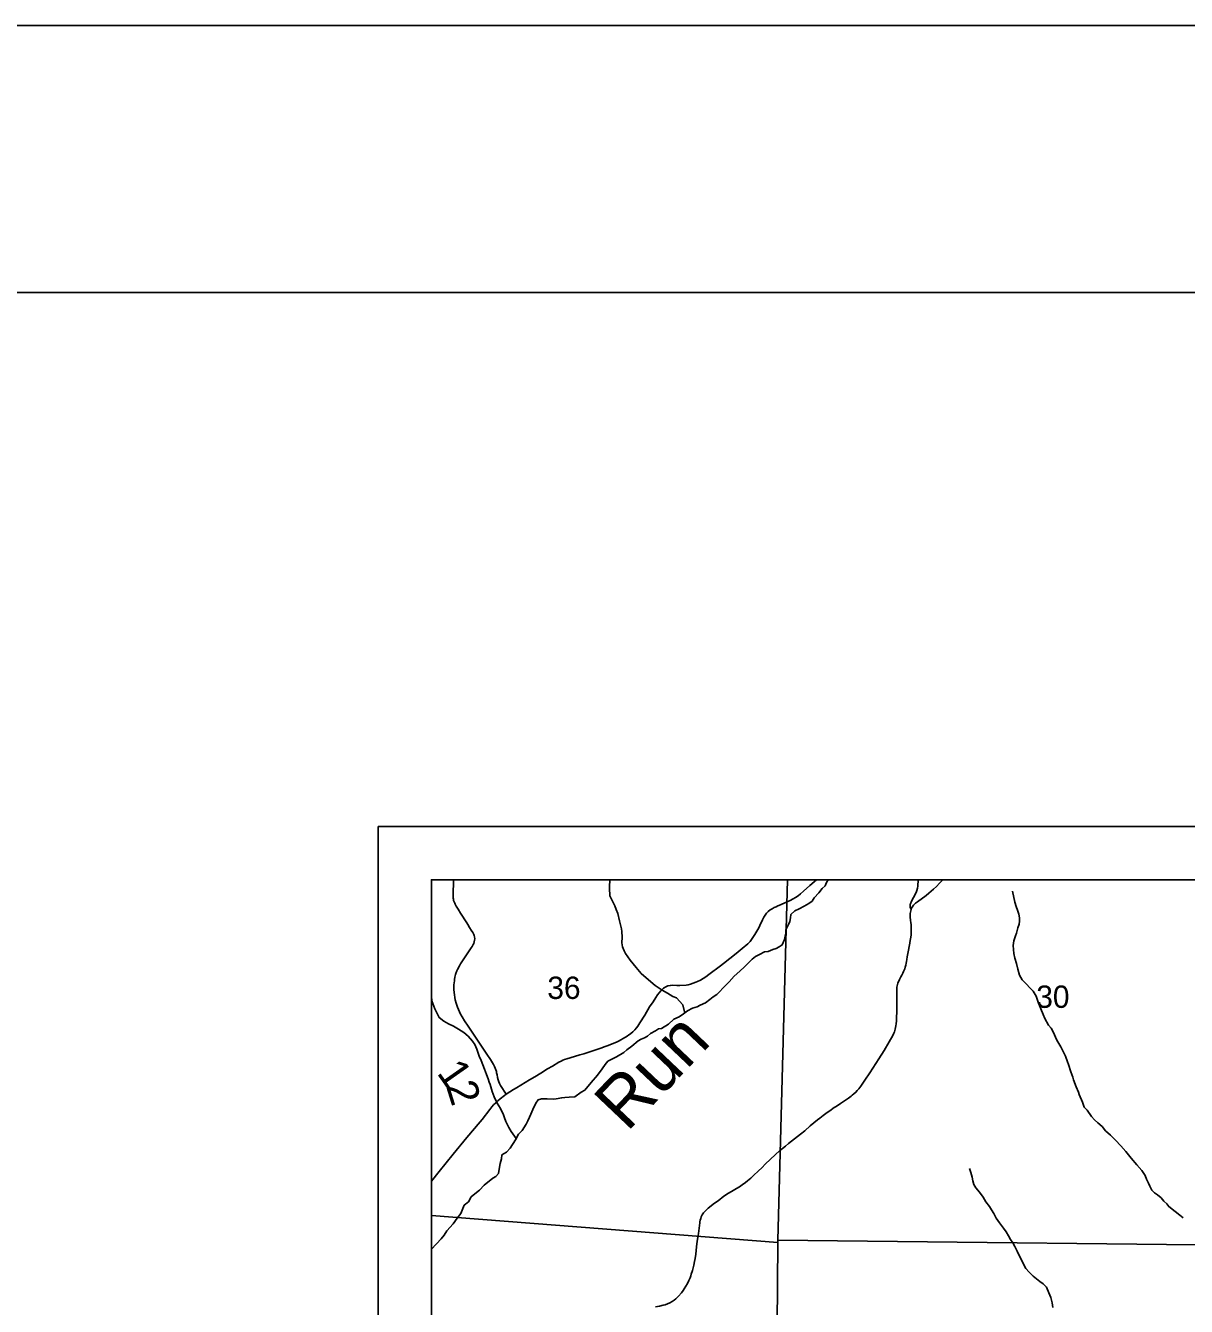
# Model space of a CAD drawing. Extents: x 0 to 34, y 0 to 22.
# Drawn here: x 17.84 to 20.014, y 19.601 to 22 of the extents above; entities that cross this region are included whole.
import ezdxf

# ---------------------------------------------------------------- set-up
doc = ezdxf.new("R2010")
doc.units = 0
for name, color, linetype in [('GM_X_Corporation', 7, 'Continuous'), ('GM_X_Minor_River', 7, 'Continuous'), ('GM_X_Minor_River_Text', 7, 'Continuous'), ('GM_X_Section_Text', 7, 'Continuous'), ('GM_X_Township_Road', 7, 'Continuous'), ('GM_X_Township_Road_Text', 7, 'Continuous'), ('SH_Border', 7, 'Continuous'), ('SH_Cut_Line', 7, 'Continuous'), ('SH_Data', 7, 'Continuous')]:
    doc.layers.add(name, color=color, linetype=linetype)

msp = doc.modelspace()

# ---------------------------------------------------------------- linework, layer by layer
at = {"layer": 'GM_X_Corporation'}
for points in [[(19.267, 20.4), (18.6, 20.4), (18.6, 19.7712), (19.2491, 19.7204), (19.2491, 19.7249)], [(21.2921, 20.4), (18.6, 20.4), (18.6, 19.2331), (18.9898, 19.2261), (20.065, 19.208), (20.254, 19.2058), (20.8916, 19.1966), (21.2652, 19.1913), (21.273, 19.5535), (21.2742, 19.6071), (21.2757, 19.6748)], [(20.2723, 20.4), (19.267, 20.4), (19.2491, 19.7249), (20.2574, 19.7138)], [(18.6, 19.7712), (18.6, 18.7129), (19.241, 18.7106), (19.2491, 19.7204)], [(19.2491, 19.7249), (20.2574, 19.7138), (20.2437, 18.6978), (19.241, 18.7106), (19.2491, 19.7204)]]:
    msp.add_lwpolyline(points, close=True, dxfattribs=at)
at = {"layer": 'GM_X_Minor_River'}
for points in [[(19.0747, 20.1503), (19.0707, 20.1656), (19.0591, 20.1787), (19.0519, 20.1813), (19.042, 20.1876), (19.0324, 20.1932), (19.019, 20.2021), (19.0064, 20.2126), (18.993, 20.2241), (18.9833, 20.2354), (18.9721, 20.2493), (18.9636, 20.2621), (18.9609, 20.267), (18.9578, 20.2746), (18.9569, 20.2815), (18.9571, 20.2925), (18.957, 20.3031), (18.9558, 20.3081), (18.9525, 20.3232), (18.9493, 20.3369), (18.9461, 20.3445), (18.9434, 20.3513), (18.9391, 20.36), (18.9344, 20.3698), (18.9338, 20.3842), (18.9337, 20.3892), (18.9344, 20.3976), (18.9346, 20.4)], [(19.1777, 20.2285), (19.1862, 20.2366), (19.1926, 20.2428), (19.2008, 20.2513), (19.2072, 20.2563), (19.2143, 20.2598), (19.2241, 20.2649), (19.2309, 20.2658), (19.2395, 20.2694), (19.2456, 20.2714), (19.2516, 20.2745), (19.2572, 20.278), (19.2616, 20.2883), (19.2626, 20.2941), (19.2637, 20.3002), (19.264, 20.3059), (19.268, 20.3151), (19.2713, 20.322), (19.2727, 20.3289), (19.2734, 20.3346), (19.2809, 20.3415), (19.2888, 20.3458), (19.2985, 20.3502), (19.3068, 20.3552), (19.3132, 20.3599), (19.3169, 20.3661), (19.3254, 20.3757), (19.3318, 20.3834), (19.3377, 20.3884), (19.3399, 20.3946), (19.3431, 20.4)], [(20.0078, 19.7669), (20.0021, 19.7718), (19.9933, 19.7785), (19.981, 19.7878), (19.9772, 19.7931), (19.9718, 19.798), (19.9668, 19.804), (19.9599, 19.81), (19.9541, 19.8137), (19.9495, 19.8186), (19.9456, 19.8257), (19.9429, 19.8314), (19.9394, 19.8393), (19.9366, 19.8462), (19.9308, 19.8552), (19.9212, 19.8661), (19.9104, 19.8785), (19.9004, 19.8909), (19.8911, 19.9018), (19.8811, 19.9123), (19.8719, 19.9213), (19.8627, 19.9296), (19.8562, 19.9375), (19.8481, 19.9446), (19.842, 19.9502), (19.8366, 19.9566), (19.8281, 19.9683), (19.8227, 19.9739), (19.8192, 19.9834), (19.8133, 19.9974), (19.8117, 20.0023), (19.8074, 20.0121), (19.8026, 20.025), (19.8011, 20.0299), (19.7975, 20.0401), (19.7931, 20.0542), (19.7916, 20.0591), (19.7876, 20.0693), (19.7814, 20.0821), (19.7787, 20.0871), (19.7736, 20.0961), (19.7701, 20.1021), (19.7658, 20.1127), (19.7611, 20.1218), (19.7561, 20.1274), (19.7491, 20.1399), (19.746, 20.1478), (19.7416, 20.1581), (19.7365, 20.1709), (19.7326, 20.1819), (19.7268, 20.1913), (19.721, 20.1973), (19.7145, 20.2045), (19.7068, 20.2124), (19.7017, 20.2214), (19.6985, 20.2324), (19.6957, 20.243), (19.6929, 20.2529), (19.6909, 20.262), (19.69, 20.2696), (19.6896, 20.2768), (19.6906, 20.2856), (19.6938, 20.2948), (19.696, 20.3001), (19.6985, 20.3101), (19.7007, 20.3169), (19.7014, 20.3227), (19.7013, 20.3287), (19.7001, 20.3352), (19.6977, 20.3432), (19.6953, 20.35), (19.6929, 20.3579), (19.6882, 20.3788)], [(18.6, 19.7078), (18.6186, 19.7271), (18.6241, 19.7344), (18.6289, 19.7425), (18.6409, 19.7556), (18.6483, 19.7663), (18.655, 19.7748), (18.6616, 19.7902), (18.6694, 19.7967), (18.6742, 19.806), (18.6813, 19.8118), (18.6899, 19.8187), (18.6989, 19.828), (18.715, 19.8412), (18.721, 19.844), (18.7254, 19.8497), (18.7272, 19.8578), (18.729, 19.8684), (18.7315, 19.8772), (18.7321, 19.8845), (18.7408, 19.8899), (18.7475, 19.8969), (18.7575, 19.9127), (18.763, 19.9234), (18.7701, 19.93), (18.7775, 19.9423), (18.7808, 19.9484), (18.7837, 19.9553), (18.7863, 19.961), (18.79, 19.9695), (18.7955, 19.9814), (18.7999, 19.9875), (18.8063, 19.9895), (18.8169, 19.9897), (18.8279, 19.9887), (18.834, 19.9896), (18.8441, 19.9916), (18.8502, 19.9921), (18.8578, 19.993), (18.8684, 19.9931), (18.8803, 20.0021), (18.8871, 20.006), (18.8994, 20.0199), (18.9109, 20.0341), (18.9198, 20.0457), (18.9254, 20.0538), (18.9302, 20.0599), (18.9464, 20.0682), (18.9607, 20.0764), (18.9663, 20.0814), (18.9756, 20.0884), (18.9872, 20.0985), (18.9932, 20.1012), (18.9989, 20.1036), (19.0045, 20.1071), (19.0105, 20.1121), (19.0195, 20.1168), (19.0251, 20.1204), (19.0312, 20.1216), (19.0443, 20.1294), (19.054, 20.1387), (19.0638, 20.1434), (19.0724, 20.1485), (19.0795, 20.1543), (19.0893, 20.1594), (19.098, 20.1622), (19.1036, 20.1649), (19.1134, 20.1693), (19.1216, 20.1755), (19.128, 20.1805), (19.1344, 20.1852), (19.14, 20.1906), (19.1456, 20.1968), (19.1519, 20.2033), (19.1575, 20.2087), (19.1668, 20.2192), (19.1777, 20.2285)], [(18.7587, 19.9151), (18.7497, 19.9281), (18.745, 19.9357), (18.7395, 19.947), (18.7372, 19.9542), (18.7348, 19.9599), (18.7297, 19.9712), (18.7231, 19.9814), (18.7173, 19.9931), (18.7141, 20.0033), (18.7098, 20.0162), (18.7085, 20.0211), (18.7066, 20.0268), (18.703, 20.0351), (18.6995, 20.045), (18.6932, 20.0616), (18.6897, 20.0692), (18.6853, 20.0824), (18.6814, 20.0911), (18.6771, 20.0979), (18.6691, 20.1069), (18.6606, 20.114), (18.6507, 20.1203), (18.6411, 20.1255), (18.632, 20.13), (18.6232, 20.1352), (18.6148, 20.1419), (18.6113, 20.1483), (18.6062, 20.1581), (18.6027, 20.1679), (18.6011, 20.1733), (18.6, 20.1812)], [(19.7642, 19.5985), (19.7626, 19.6076), (19.7601, 19.6175), (19.7566, 19.6262), (19.7519, 19.6368), (19.7461, 19.6428), (19.7396, 19.6473), (19.7331, 19.6525), (19.7274, 19.6574), (19.7193, 19.6649), (19.7132, 19.672), (19.7034, 19.6909), (19.6972, 19.7045), (19.6925, 19.7128), (19.689, 19.7196), (19.6844, 19.726), (19.6812, 19.7332), (19.6766, 19.7407), (19.6716, 19.7475), (19.6638, 19.7573), (19.6577, 19.766), (19.6537, 19.7746), (19.6491, 19.7814), (19.6452, 19.7878), (19.6386, 19.7969), (19.6332, 19.8052), (19.6266, 19.815), (19.6197, 19.8229), (19.6162, 19.8289), (19.6142, 19.8357), (19.6126, 19.8426), (19.6102, 19.8517), (19.6078, 19.8592)]]:
    msp.add_lwpolyline(points, dxfattribs=at)
at = {"layer": 'GM_X_Township_Road'}
for points in [[(18.6436, 20.3564), (18.6426, 20.3584), (18.6417, 20.3613), (18.6412, 20.3633), (18.6409, 20.3657), (18.6408, 20.368), (18.6409, 20.3824), (18.6411, 20.3882), (18.6414, 20.3942), (18.6417, 20.4)], [(19.249, 20.3509), (19.2507, 20.3517), (19.2719, 20.3613), (19.2773, 20.364), (19.282, 20.3667), (19.2867, 20.3697), (19.2915, 20.3736), (19.297, 20.3783), (19.309, 20.3889), (19.3213, 20.4)], [(19.4984, 20.3444), (19.4977, 20.3461), (19.497, 20.3482), (19.4968, 20.3499), (19.4967, 20.3519), (19.4968, 20.3536), (19.4972, 20.3551), (19.4978, 20.3568), (19.4985, 20.3583), (19.5005, 20.3622), (19.5032, 20.367), (19.506, 20.3724), (19.5085, 20.3777), (19.5093, 20.3798), (19.5106, 20.3845), (19.5109, 20.3877), (19.5113, 20.3923), (19.5115, 20.3957), (19.5116, 20.3983), (19.5117, 20.4)], [(19.4984, 20.3444), (19.4991, 20.3465), (19.5002, 20.3488), (19.5015, 20.3508), (19.5028, 20.3525), (19.5046, 20.3543), (19.507, 20.3563), (19.5106, 20.3589), (19.5267, 20.3702), (19.532, 20.3746), (19.5404, 20.3822), (19.5458, 20.3873), (19.5517, 20.3934), (19.5578, 20.4)], [(18.74, 19.9983), (18.7294, 20.0145), (18.7273, 20.0183), (18.7262, 20.0215), (18.725, 20.0253), (18.7241, 20.0293), (18.7231, 20.0344), (18.7222, 20.0382), (18.7218, 20.0406), (18.7208, 20.0439), (18.7197, 20.0468), (18.7184, 20.0499), (18.7163, 20.0537), (18.7105, 20.0634), (18.7037, 20.0735), (18.6879, 20.0973), (18.669, 20.1254), (18.6623, 20.1355), (18.6575, 20.1431), (18.6548, 20.148), (18.6524, 20.1528), (18.6506, 20.1567), (18.6488, 20.1616), (18.6464, 20.1691), (18.6448, 20.1751), (18.6438, 20.1795), (18.6431, 20.1842), (18.6426, 20.1887), (18.6422, 20.1945), (18.6422, 20.2007), (18.6423, 20.2032), (18.643, 20.2105), (18.6434, 20.213), (18.6442, 20.2175), (18.6453, 20.2223), (18.646, 20.2245), (18.6477, 20.2291), (18.649, 20.2321), (18.6525, 20.2389), (18.6547, 20.2426), (18.6584, 20.2483), (18.6747, 20.2723), (18.6765, 20.275), (18.6784, 20.2785), (18.6793, 20.2805), (18.6803, 20.2835), (18.681, 20.287), (18.6812, 20.2895), (18.6809, 20.2928), (18.6803, 20.2953), (18.6793, 20.2975), (18.6774, 20.301), (18.6748, 20.3055), (18.6715, 20.3108), (18.6685, 20.3163), (18.6664, 20.3195), (18.6546, 20.3371), (18.6499, 20.3447), (18.6466, 20.3505), (18.6445, 20.3544), (18.6436, 20.3564)], [(18.9676, 20.1076), (18.9693, 20.1088), (18.9737, 20.1121), (18.9775, 20.1153), (18.9812, 20.1187), (18.984, 20.1223), (18.9864, 20.1257), (18.9907, 20.132), (18.9998, 20.1465), (19.0088, 20.1619), (19.0153, 20.1716), (19.0204, 20.1797), (19.0237, 20.1844), (19.0269, 20.1884), (19.0298, 20.1918), (19.0322, 20.1945), (19.0349, 20.1967), (19.0389, 20.1991), (19.0431, 20.201), (19.0476, 20.2019), (19.0517, 20.2022), (19.0594, 20.202), (19.0652, 20.2019), (19.0769, 20.2026), (19.0807, 20.2034), (19.0854, 20.2046), (19.0901, 20.206), (19.0956, 20.2081), (19.0983, 20.2092), (19.104, 20.212), (19.1093, 20.2153), (19.114, 20.2184), (19.1194, 20.2222), (19.1412, 20.2386), (19.1468, 20.2429), (19.1711, 20.262), (19.1784, 20.2681), (19.1823, 20.2713), (19.1928, 20.2802), (19.1945, 20.2818), (19.1968, 20.2843), (19.1984, 20.2864), (19.206, 20.2974), (19.2077, 20.3003), (19.2132, 20.31), (19.2154, 20.3144), (19.2203, 20.3252), (19.2229, 20.3302), (19.2249, 20.3337), (19.2276, 20.3375), (19.2307, 20.3404), (19.2343, 20.3435), (19.2382, 20.3457), (19.242, 20.3478), (19.2456, 20.3493), (19.249, 20.3509)], [(19.0195, 19.5997), (19.0274, 19.6013), (19.0342, 19.603), (19.0379, 19.604), (19.0421, 19.6055), (19.0465, 19.6074), (19.051, 19.6098), (19.0546, 19.6125), (19.058, 19.6149), (19.0605, 19.6172), (19.0631, 19.6197), (19.0683, 19.626), (19.0716, 19.6308), (19.0735, 19.6338), (19.0764, 19.6384), (19.0795, 19.6439), (19.0823, 19.6491), (19.0845, 19.654), (19.0858, 19.6578), (19.0868, 19.661), (19.0889, 19.6683), (19.0914, 19.6783), (19.0928, 19.6846), (19.094, 19.6907), (19.095, 19.6989), (19.0958, 19.7057), (19.0965, 19.7121), (19.0979, 19.7229), (19.0989, 19.7297), (19.1001, 19.7376), (19.1027, 19.7573), (19.103, 19.7591), (19.1036, 19.7622), (19.1044, 19.7655), (19.1054, 19.7688), (19.1072, 19.7723), (19.1082, 19.7742), (19.1099, 19.7763), (19.1114, 19.7779), (19.115, 19.7815), (19.1183, 19.7845), (19.1239, 19.7892), (19.1278, 19.7923), (19.132, 19.7953), (19.1369, 19.7988), (19.148, 19.8071), (19.1566, 19.8126), (19.1618, 19.8162), (19.1716, 19.8218), (19.1768, 19.825), (19.1823, 19.8286), (19.1882, 19.8327), (19.1923, 19.8359), (19.1982, 19.8407), (19.2042, 19.8465), (19.2122, 19.8543), (19.2194, 19.8612), (19.2253, 19.867), (19.2349, 19.8765), (19.2439, 19.8849), (19.2529, 19.8929), (19.2576, 19.8967), (19.263, 19.9012), (19.2689, 19.9057), (19.2911, 19.9232), (19.2992, 19.9298), (19.3094, 19.939), (19.3165, 19.9449), (19.3231, 19.95), (19.3276, 19.9534), (19.3339, 19.9581), (19.3414, 19.9637), (19.3479, 19.9684), (19.3526, 19.9718), (19.3599, 19.9767), (19.3664, 19.9809), (19.3738, 19.9859), (19.3814, 19.9909), (19.386, 19.9944), (19.3884, 19.9963), (19.3913, 19.9988), (19.395, 20.002), (19.3976, 20.0049), (19.4007, 20.0085), (19.4042, 20.013), (19.4081, 20.0187), (19.4121, 20.0245), (19.4212, 20.0381), (19.4381, 20.0647), (19.448, 20.0803), (19.4577, 20.0964), (19.4642, 20.1083), (19.4661, 20.1123), (19.4673, 20.1154), (19.4687, 20.12), (19.4695, 20.1235), (19.47, 20.1264), (19.4706, 20.13), (19.4711, 20.136), (19.4714, 20.1419), (19.4715, 20.1524), (19.4717, 20.193), (19.4718, 20.1958), (19.472, 20.1985), (19.4725, 20.201), (19.4738, 20.2062), (19.477, 20.2132), (19.4795, 20.2182), (19.4814, 20.2214), (19.4832, 20.2248), (19.4845, 20.2282), (19.4865, 20.2332), (19.4874, 20.2364), (19.4885, 20.2402), (19.4893, 20.2437), (19.4901, 20.2469), (19.4906, 20.2505), (19.4914, 20.2555), (19.4924, 20.2621), (19.4959, 20.2809), (19.4963, 20.2827), (19.4983, 20.2961), (19.4988, 20.3013), (19.4986, 20.3128), (19.4984, 20.3157), (19.498, 20.3199), (19.4976, 20.3234), (19.497, 20.3308), (19.4967, 20.3365), (19.4973, 20.3394), (19.4977, 20.342), (19.4984, 20.3444)], [(18.8495, 20.0633), (18.8537, 20.0648), (18.8597, 20.0664), (18.878, 20.0717), (18.8856, 20.0741), (18.9172, 20.0843), (18.9257, 20.0874), (18.9314, 20.0896), (18.9477, 20.0966), (18.9514, 20.0984), (18.9623, 20.1043), (18.965, 20.106), (18.9676, 20.1076)], [(18.6, 19.8353), (18.6147, 19.8534), (18.6407, 19.8858), (18.6666, 19.9169), (18.6915, 19.9465), (18.6949, 19.9508), (18.7092, 19.9694), (18.7131, 19.9747), (18.7165, 19.9786), (18.7205, 19.9824), (18.7244, 19.9857), (18.7289, 19.9894), (18.7371, 19.996), (18.74, 19.9983), (18.7472, 20.003), (18.754, 20.0072), (18.7595, 20.0105), (18.784, 20.0253), (18.7938, 20.0311), (18.8051, 20.0379), (18.8176, 20.0455), (18.8268, 20.051), (18.8388, 20.0581), (18.8429, 20.0603), (18.846, 20.0618), (18.8495, 20.0633)]]:
    msp.add_lwpolyline(points, dxfattribs=at)
at = {"layer": 'SH_Border'}
msp.add_lwpolyline([(1.5, 21.5), (33.5, 21.5), (33.5, 0.5), (1.5, 0.5)], close=True, dxfattribs=at)
at = {"layer": 'SH_Cut_Line'}
msp.add_lwpolyline([(0, 0), (34, 0), (34, 22), (0, 22)], close=True, dxfattribs=at)
at = {"layer": 'SH_Data'}
for points in [[(18.5, 20.5), (25.5, 20.5), (25.5, 13.5), (18.5, 13.5)], [(18.6, 20.4), (25.4, 20.4), (25.4, 13.6), (18.6, 13.6)]]:
    msp.add_lwpolyline(points, close=True, dxfattribs=at)

# ---------------------------------------------------------------- texts
at = {"layer": 'GM_X_Minor_River_Text'}
msp.add_text('Run', height=0.09468, rotation=46.4704, dxfattribs=at).set_placement((18.9664, 19.926))
at = {"layer": 'GM_X_Section_Text'}
for s, p in [('36', (18.8171, 20.1767)), ('30', (19.7329, 20.16))]:
    msp.add_text(s, height=0.04186, rotation=0, dxfattribs=at).set_placement(p)
at = {"layer": 'GM_X_Township_Road_Text'}
for s, rotation, p in [('1', 305.0322, (18.609, 20.0381)), ('2', 287.3438, (18.6271, 20.0136))]:
    msp.add_text(s, height=0.0568, rotation=rotation, dxfattribs=at).set_placement(p)

doc.saveas('drawing.dxf')
